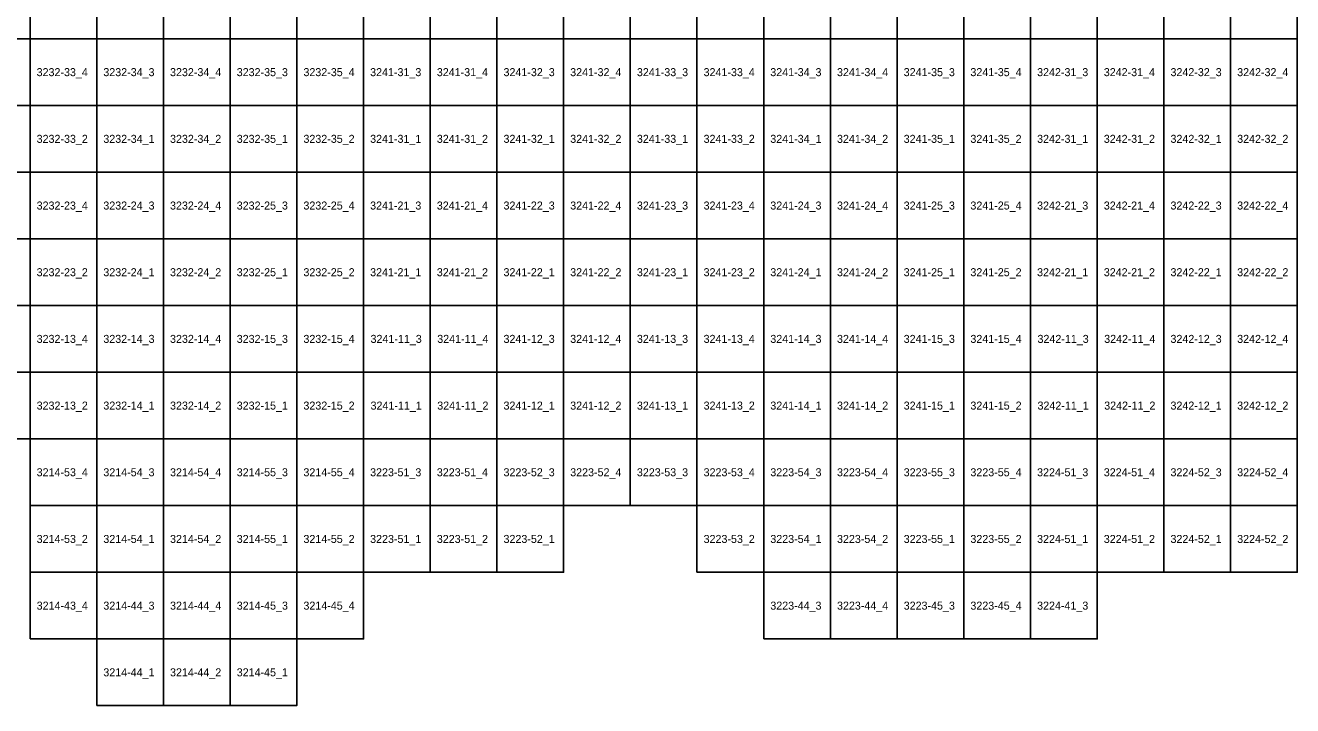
# Model space of a CAD drawing. Extents: x 312500 to 765000, y 172500 to 440000.
# Drawn here: x 437325 to 484827, y 240000 to 265505 of the extents above; entities that cross this region are included whole.
import ezdxf

# ---------------------------------------------------------------- set-up
doc = ezdxf.new("R2010")
doc.units = 0
doc.layers.add('Topo5_ramis_TKS2025', color=7, linetype='Continuous')
doc.layers.add('Topo5_ramis_TKS2025_Nr', color=7, linetype='Continuous')

msp = doc.modelspace()

# ---------------------------------------------------------------- linework, layer by layer
at = {"layer": 'Topo5_ramis_TKS2025'}
for points in [[(435000, 265000), (435000, 267500), (437500, 267500), (437500, 265000), (435000, 265000)], [(437500, 265000), (437500, 267500), (440000, 267500), (440000, 265000), (437500, 265000)], [(440000, 265000), (440000, 267500), (442500, 267500), (442500, 265000), (440000, 265000)], [(442500, 265000), (442500, 267500), (445000, 267500), (445000, 265000), (442500, 265000)], [(445000, 265000), (445000, 267500), (447500, 267500), (447500, 265000), (445000, 265000)], [(447500, 265000), (447500, 267500), (450000, 267500), (450000, 265000), (447500, 265000)], [(450000, 265000), (450000, 267500), (452500, 267500), (452500, 265000), (450000, 265000)], [(452500, 265000), (452500, 267500), (455000, 267500), (455000, 265000), (452500, 265000)], [(455000, 265000), (455000, 267500), (457500, 267500), (457500, 265000), (455000, 265000)], [(457500, 265000), (457500, 267500), (460000, 267500), (460000, 265000), (457500, 265000)], [(460000, 265000), (460000, 267500), (462500, 267500), (462500, 265000), (460000, 265000)], [(462500, 265000), (462500, 267500), (465000, 267500), (465000, 265000), (462500, 265000)], [(465000, 265000), (465000, 267500), (467500, 267500), (467500, 265000), (465000, 265000)], [(467500, 265000), (467500, 267500), (470000, 267500), (470000, 265000), (467500, 265000)], [(470000, 265000), (470000, 267500), (472500, 267500), (472500, 265000), (470000, 265000)], [(472500, 265000), (472500, 267500), (475000, 267500), (475000, 265000), (472500, 265000)], [(475000, 265000), (475000, 267500), (477500, 267500), (477500, 265000), (475000, 265000)], [(477500, 265000), (477500, 267500), (480000, 267500), (480000, 265000), (477500, 265000)], [(480000, 265000), (480000, 267500), (482500, 267500), (482500, 265000), (480000, 265000)], [(482500, 265000), (482500, 267500), (485000, 267500), (485000, 265000), (482500, 265000)], [(435000, 262500), (435000, 265000), (437500, 265000), (437500, 262500), (435000, 262500)], [(437500, 262500), (437500, 265000), (440000, 265000), (440000, 262500), (437500, 262500)], [(440000, 262500), (440000, 265000), (442500, 265000), (442500, 262500), (440000, 262500)], [(442500, 262500), (442500, 265000), (445000, 265000), (445000, 262500), (442500, 262500)], [(445000, 262500), (445000, 265000), (447500, 265000), (447500, 262500), (445000, 262500)], [(447500, 262500), (447500, 265000), (450000, 265000), (450000, 262500), (447500, 262500)], [(450000, 262500), (450000, 265000), (452500, 265000), (452500, 262500), (450000, 262500)], [(452500, 262500), (452500, 265000), (455000, 265000), (455000, 262500), (452500, 262500)], [(455000, 262500), (455000, 265000), (457500, 265000), (457500, 262500), (455000, 262500)], [(457500, 262500), (457500, 265000), (460000, 265000), (460000, 262500), (457500, 262500)], [(460000, 262500), (460000, 265000), (462500, 265000), (462500, 262500), (460000, 262500)], [(462500, 262500), (462500, 265000), (465000, 265000), (465000, 262500), (462500, 262500)], [(465000, 262500), (465000, 265000), (467500, 265000), (467500, 262500), (465000, 262500)], [(467500, 262500), (467500, 265000), (470000, 265000), (470000, 262500), (467500, 262500)], [(470000, 262500), (470000, 265000), (472500, 265000), (472500, 262500), (470000, 262500)], [(472500, 262500), (472500, 265000), (475000, 265000), (475000, 262500), (472500, 262500)], [(475000, 262500), (475000, 265000), (477500, 265000), (477500, 262500), (475000, 262500)], [(477500, 262500), (477500, 265000), (480000, 265000), (480000, 262500), (477500, 262500)], [(480000, 262500), (480000, 265000), (482500, 265000), (482500, 262500), (480000, 262500)], [(482500, 262500), (482500, 265000), (485000, 265000), (485000, 262500), (482500, 262500)], [(435000, 260000), (435000, 262500), (437500, 262500), (437500, 260000), (435000, 260000)], [(437500, 260000), (437500, 262500), (440000, 262500), (440000, 260000), (437500, 260000)], [(440000, 260000), (440000, 262500), (442500, 262500), (442500, 260000), (440000, 260000)], [(442500, 260000), (442500, 262500), (445000, 262500), (445000, 260000), (442500, 260000)], [(445000, 260000), (445000, 262500), (447500, 262500), (447500, 260000), (445000, 260000)], [(447500, 260000), (447500, 262500), (450000, 262500), (450000, 260000), (447500, 260000)], [(450000, 260000), (450000, 262500), (452500, 262500), (452500, 260000), (450000, 260000)], [(452500, 260000), (452500, 262500), (455000, 262500), (455000, 260000), (452500, 260000)], [(455000, 260000), (455000, 262500), (457500, 262500), (457500, 260000), (455000, 260000)], [(457500, 260000), (457500, 262500), (460000, 262500), (460000, 260000), (457500, 260000)], [(460000, 260000), (460000, 262500), (462500, 262500), (462500, 260000), (460000, 260000)], [(462500, 260000), (462500, 262500), (465000, 262500), (465000, 260000), (462500, 260000)], [(465000, 260000), (465000, 262500), (467500, 262500), (467500, 260000), (465000, 260000)], [(467500, 260000), (467500, 262500), (470000, 262500), (470000, 260000), (467500, 260000)], [(470000, 260000), (470000, 262500), (472500, 262500), (472500, 260000), (470000, 260000)], [(472500, 260000), (472500, 262500), (475000, 262500), (475000, 260000), (472500, 260000)], [(475000, 260000), (475000, 262500), (477500, 262500), (477500, 260000), (475000, 260000)], [(477500, 260000), (477500, 262500), (480000, 262500), (480000, 260000), (477500, 260000)], [(480000, 260000), (480000, 262500), (482500, 262500), (482500, 260000), (480000, 260000)], [(482500, 260000), (482500, 262500), (485000, 262500), (485000, 260000), (482500, 260000)], [(435000, 257500), (435000, 260000), (437500, 260000), (437500, 257500), (435000, 257500)], [(437500, 257500), (437500, 260000), (440000, 260000), (440000, 257500), (437500, 257500)], [(440000, 257500), (440000, 260000), (442500, 260000), (442500, 257500), (440000, 257500)], [(442500, 257500), (442500, 260000), (445000, 260000), (445000, 257500), (442500, 257500)], [(445000, 257500), (445000, 260000), (447500, 260000), (447500, 257500), (445000, 257500)], [(447500, 257500), (447500, 260000), (450000, 260000), (450000, 257500), (447500, 257500)], [(450000, 257500), (450000, 260000), (452500, 260000), (452500, 257500), (450000, 257500)], [(452500, 257500), (452500, 260000), (455000, 260000), (455000, 257500), (452500, 257500)], [(455000, 257500), (455000, 260000), (457500, 260000), (457500, 257500), (455000, 257500)], [(457500, 257500), (457500, 260000), (460000, 260000), (460000, 257500), (457500, 257500)], [(460000, 257500), (460000, 260000), (462500, 260000), (462500, 257500), (460000, 257500)], [(462500, 257500), (462500, 260000), (465000, 260000), (465000, 257500), (462500, 257500)], [(465000, 257500), (465000, 260000), (467500, 260000), (467500, 257500), (465000, 257500)], [(467500, 257500), (467500, 260000), (470000, 260000), (470000, 257500), (467500, 257500)], [(470000, 257500), (470000, 260000), (472500, 260000), (472500, 257500), (470000, 257500)], [(472500, 257500), (472500, 260000), (475000, 260000), (475000, 257500), (472500, 257500)], [(475000, 257500), (475000, 260000), (477500, 260000), (477500, 257500), (475000, 257500)], [(477500, 257500), (477500, 260000), (480000, 260000), (480000, 257500), (477500, 257500)], [(480000, 257500), (480000, 260000), (482500, 260000), (482500, 257500), (480000, 257500)], [(482500, 257500), (482500, 260000), (485000, 260000), (485000, 257500), (482500, 257500)], [(435000, 255000), (435000, 257500), (437500, 257500), (437500, 255000), (435000, 255000)], [(437500, 255000), (437500, 257500), (440000, 257500), (440000, 255000), (437500, 255000)], [(440000, 255000), (440000, 257500), (442500, 257500), (442500, 255000), (440000, 255000)], [(442500, 255000), (442500, 257500), (445000, 257500), (445000, 255000), (442500, 255000)], [(445000, 255000), (445000, 257500), (447500, 257500), (447500, 255000), (445000, 255000)], [(447500, 255000), (447500, 257500), (450000, 257500), (450000, 255000), (447500, 255000)], [(450000, 255000), (450000, 257500), (452500, 257500), (452500, 255000), (450000, 255000)], [(452500, 255000), (452500, 257500), (455000, 257500), (455000, 255000), (452500, 255000)], [(455000, 255000), (455000, 257500), (457500, 257500), (457500, 255000), (455000, 255000)], [(457500, 255000), (457500, 257500), (460000, 257500), (460000, 255000), (457500, 255000)], [(460000, 255000), (460000, 257500), (462500, 257500), (462500, 255000), (460000, 255000)], [(462500, 255000), (462500, 257500), (465000, 257500), (465000, 255000), (462500, 255000)], [(465000, 255000), (465000, 257500), (467500, 257500), (467500, 255000), (465000, 255000)], [(467500, 255000), (467500, 257500), (470000, 257500), (470000, 255000), (467500, 255000)], [(470000, 255000), (470000, 257500), (472500, 257500), (472500, 255000), (470000, 255000)], [(472500, 255000), (472500, 257500), (475000, 257500), (475000, 255000), (472500, 255000)], [(475000, 255000), (475000, 257500), (477500, 257500), (477500, 255000), (475000, 255000)], [(477500, 255000), (477500, 257500), (480000, 257500), (480000, 255000), (477500, 255000)], [(480000, 255000), (480000, 257500), (482500, 257500), (482500, 255000), (480000, 255000)], [(482500, 255000), (482500, 257500), (485000, 257500), (485000, 255000), (482500, 255000)], [(435000, 252500), (435000, 255000), (437500, 255000), (437500, 252500), (435000, 252500)], [(437500, 252500), (437500, 255000), (440000, 255000), (440000, 252500), (437500, 252500)], [(440000, 252500), (440000, 255000), (442500, 255000), (442500, 252500), (440000, 252500)], [(442500, 252500), (442500, 255000), (445000, 255000), (445000, 252500), (442500, 252500)], [(445000, 252500), (445000, 255000), (447500, 255000), (447500, 252500), (445000, 252500)], [(447500, 252500), (447500, 255000), (450000, 255000), (450000, 252500), (447500, 252500)], [(450000, 252500), (450000, 255000), (452500, 255000), (452500, 252500), (450000, 252500)], [(452500, 252500), (452500, 255000), (455000, 255000), (455000, 252500), (452500, 252500)], [(455000, 252500), (455000, 255000), (457500, 255000), (457500, 252500), (455000, 252500)], [(457500, 252500), (457500, 255000), (460000, 255000), (460000, 252500), (457500, 252500)], [(460000, 252500), (460000, 255000), (462500, 255000), (462500, 252500), (460000, 252500)], [(462500, 252500), (462500, 255000), (465000, 255000), (465000, 252500), (462500, 252500)], [(465000, 252500), (465000, 255000), (467500, 255000), (467500, 252500), (465000, 252500)], [(467500, 252500), (467500, 255000), (470000, 255000), (470000, 252500), (467500, 252500)], [(470000, 252500), (470000, 255000), (472500, 255000), (472500, 252500), (470000, 252500)], [(472500, 252500), (472500, 255000), (475000, 255000), (475000, 252500), (472500, 252500)], [(475000, 252500), (475000, 255000), (477500, 255000), (477500, 252500), (475000, 252500)], [(477500, 252500), (477500, 255000), (480000, 255000), (480000, 252500), (477500, 252500)], [(480000, 252500), (480000, 255000), (482500, 255000), (482500, 252500), (480000, 252500)], [(482500, 252500), (482500, 255000), (485000, 255000), (485000, 252500), (482500, 252500)], [(435000, 250000), (435000, 252500), (437500, 252500), (437500, 250000), (435000, 250000)], [(437500, 250000), (437500, 252500), (440000, 252500), (440000, 250000), (437500, 250000)], [(440000, 250000), (440000, 252500), (442500, 252500), (442500, 250000), (440000, 250000)], [(442500, 250000), (442500, 252500), (445000, 252500), (445000, 250000), (442500, 250000)], [(445000, 250000), (445000, 252500), (447500, 252500), (447500, 250000), (445000, 250000)], [(447500, 250000), (447500, 252500), (450000, 252500), (450000, 250000), (447500, 250000)], [(450000, 250000), (450000, 252500), (452500, 252500), (452500, 250000), (450000, 250000)], [(452500, 250000), (452500, 252500), (455000, 252500), (455000, 250000), (452500, 250000)], [(455000, 250000), (455000, 252500), (457500, 252500), (457500, 250000), (455000, 250000)], [(457500, 250000), (457500, 252500), (460000, 252500), (460000, 250000), (457500, 250000)], [(460000, 250000), (460000, 252500), (462500, 252500), (462500, 250000), (460000, 250000)], [(462500, 250000), (462500, 252500), (465000, 252500), (465000, 250000), (462500, 250000)], [(465000, 250000), (465000, 252500), (467500, 252500), (467500, 250000), (465000, 250000)], [(467500, 250000), (467500, 252500), (470000, 252500), (470000, 250000), (467500, 250000)], [(470000, 250000), (470000, 252500), (472500, 252500), (472500, 250000), (470000, 250000)], [(472500, 250000), (472500, 252500), (475000, 252500), (475000, 250000), (472500, 250000)], [(475000, 250000), (475000, 252500), (477500, 252500), (477500, 250000), (475000, 250000)], [(477500, 250000), (477500, 252500), (480000, 252500), (480000, 250000), (477500, 250000)], [(480000, 250000), (480000, 252500), (482500, 252500), (482500, 250000), (480000, 250000)], [(482500, 250000), (482500, 252500), (485000, 252500), (485000, 250000), (482500, 250000)], [(437500, 247500), (437500, 250000), (440000, 250000), (440000, 247500), (437500, 247500)], [(440000, 247500), (440000, 250000), (442500, 250000), (442500, 247500), (440000, 247500)], [(442500, 247500), (442500, 250000), (445000, 250000), (445000, 247500), (442500, 247500)], [(445000, 247500), (445000, 250000), (447500, 250000), (447500, 247500), (445000, 247500)], [(447500, 247500), (447500, 250000), (450000, 250000), (450000, 247500), (447500, 247500)], [(450000, 247500), (450000, 250000), (452500, 250000), (452500, 247500), (450000, 247500)], [(452500, 247500), (452500, 250000), (455000, 250000), (455000, 247500), (452500, 247500)], [(455000, 247500), (455000, 250000), (457500, 250000), (457500, 247500), (455000, 247500)], [(457500, 247500), (457500, 250000), (460000, 250000), (460000, 247500), (457500, 247500)], [(460000, 247500), (460000, 250000), (462500, 250000), (462500, 247500), (460000, 247500)], [(462500, 247500), (462500, 250000), (465000, 250000), (465000, 247500), (462500, 247500)], [(465000, 247500), (465000, 250000), (467500, 250000), (467500, 247500), (465000, 247500)], [(467500, 247500), (467500, 250000), (470000, 250000), (470000, 247500), (467500, 247500)], [(470000, 247500), (470000, 250000), (472500, 250000), (472500, 247500), (470000, 247500)], [(472500, 247500), (472500, 250000), (475000, 250000), (475000, 247500), (472500, 247500)], [(475000, 247500), (475000, 250000), (477500, 250000), (477500, 247500), (475000, 247500)], [(477500, 247500), (477500, 250000), (480000, 250000), (480000, 247500), (477500, 247500)], [(480000, 247500), (480000, 250000), (482500, 250000), (482500, 247500), (480000, 247500)], [(482500, 247500), (482500, 250000), (485000, 250000), (485000, 247500), (482500, 247500)], [(437500, 245000), (437500, 247500), (440000, 247500), (440000, 245000), (437500, 245000)], [(440000, 245000), (440000, 247500), (442500, 247500), (442500, 245000), (440000, 245000)], [(442500, 245000), (442500, 247500), (445000, 247500), (445000, 245000), (442500, 245000)], [(445000, 245000), (445000, 247500), (447500, 247500), (447500, 245000), (445000, 245000)], [(447500, 245000), (447500, 247500), (450000, 247500), (450000, 245000), (447500, 245000)], [(450000, 245000), (450000, 247500), (452500, 247500), (452500, 245000), (450000, 245000)], [(452500, 245000), (452500, 247500), (455000, 247500), (455000, 245000), (452500, 245000)], [(455000, 245000), (455000, 247500), (457500, 247500), (457500, 245000), (455000, 245000)], [(462500, 245000), (462500, 247500), (465000, 247500), (465000, 245000), (462500, 245000)], [(465000, 245000), (465000, 247500), (467500, 247500), (467500, 245000), (465000, 245000)], [(467500, 245000), (467500, 247500), (470000, 247500), (470000, 245000), (467500, 245000)], [(470000, 245000), (470000, 247500), (472500, 247500), (472500, 245000), (470000, 245000)], [(472500, 245000), (472500, 247500), (475000, 247500), (475000, 245000), (472500, 245000)], [(475000, 245000), (475000, 247500), (477500, 247500), (477500, 245000), (475000, 245000)], [(477500, 245000), (477500, 247500), (480000, 247500), (480000, 245000), (477500, 245000)], [(480000, 245000), (480000, 247500), (482500, 247500), (482500, 245000), (480000, 245000)], [(482500, 245000), (482500, 247500), (485000, 247500), (485000, 245000), (482500, 245000)], [(437500, 242500), (437500, 245000), (440000, 245000), (440000, 242500), (437500, 242500)], [(440000, 242500), (440000, 245000), (442500, 245000), (442500, 242500), (440000, 242500)], [(442500, 242500), (442500, 245000), (445000, 245000), (445000, 242500), (442500, 242500)], [(445000, 242500), (445000, 245000), (447500, 245000), (447500, 242500), (445000, 242500)], [(447500, 242500), (447500, 245000), (450000, 245000), (450000, 242500), (447500, 242500)], [(465000, 242500), (465000, 245000), (467500, 245000), (467500, 242500), (465000, 242500)], [(467500, 242500), (467500, 245000), (470000, 245000), (470000, 242500), (467500, 242500)], [(470000, 242500), (470000, 245000), (472500, 245000), (472500, 242500), (470000, 242500)], [(472500, 242500), (472500, 245000), (475000, 245000), (475000, 242500), (472500, 242500)], [(475000, 242500), (475000, 245000), (477500, 245000), (477500, 242500), (475000, 242500)], [(440000, 240000), (440000, 242500), (442500, 242500), (442500, 240000), (440000, 240000)], [(442500, 240000), (442500, 242500), (445000, 242500), (445000, 240000), (442500, 240000)], [(445000, 240000), (445000, 242500), (447500, 242500), (447500, 240000), (445000, 240000)]]:
    msp.add_lwpolyline(points, dxfattribs=at)

# ---------------------------------------------------------------- texts
at = {"layer": 'Topo5_ramis_TKS2025_Nr'}
for s, p in [('3232-33_4', (437748, 263600)), ('3232-34_3', (440248, 263600)), ('3232-34_4', (442748, 263600)), ('3232-35_3', (445248, 263600)), ('3232-35_4', (447748, 263600)), ('3241-31_3', (450248, 263600)), ('3241-31_4', (452748, 263600)), ('3241-32_3', (455248, 263600)), ('3241-32_4', (457748, 263600)), ('3241-33_3', (460248, 263600)), ('3241-33_4', (462748, 263600)), ('3241-34_3', (465248, 263600)), ('3241-34_4', (467748, 263600)), ('3241-35_3', (470248, 263600)), ('3241-35_4', (472748, 263600)), ('3242-31_3', (475248, 263600)), ('3242-31_4', (477748, 263600)), ('3242-32_3', (480248, 263600)), ('3242-32_4', (482748, 263600)), ('3232-33_2', (437748, 261100)), ('3232-34_1', (440248, 261100)), ('3232-34_2', (442748, 261100)), ('3232-35_1', (445248, 261100)), ('3232-35_2', (447748, 261100)), ('3241-31_1', (450248, 261100)), ('3241-31_2', (452748, 261100)), ('3241-32_1', (455248, 261100)), ('3241-32_2', (457748, 261100)), ('3241-33_1', (460248, 261100)), ('3241-33_2', (462748, 261100)), ('3241-34_1', (465248, 261100)), ('3241-34_2', (467748, 261100)), ('3241-35_1', (470248, 261100)), ('3241-35_2', (472748, 261100)), ('3242-31_1', (475248, 261100)), ('3242-31_2', (477748, 261100)), ('3242-32_1', (480248, 261100)), ('3242-32_2', (482748, 261100)), ('3232-23_4', (437748, 258600)), ('3232-24_3', (440248, 258600)), ('3232-24_4', (442748, 258600)), ('3232-25_3', (445248, 258600)), ('3232-25_4', (447748, 258600)), ('3241-21_3', (450248, 258600)), ('3241-21_4', (452748, 258600)), ('3241-22_3', (455248, 258600)), ('3241-22_4', (457748, 258600)), ('3241-23_3', (460248, 258600)), ('3241-23_4', (462748, 258600)), ('3241-24_3', (465248, 258600)), ('3241-24_4', (467748, 258600)), ('3241-25_3', (470248, 258600)), ('3241-25_4', (472748, 258600)), ('3242-21_3', (475248, 258600)), ('3242-21_4', (477748, 258600)), ('3242-22_3', (480248, 258600)), ('3242-22_4', (482748, 258600)), ('3232-23_2', (437748, 256100)), ('3232-24_1', (440248, 256100)), ('3232-24_2', (442748, 256100)), ('3232-25_1', (445248, 256100)), ('3232-25_2', (447748, 256100)), ('3241-21_1', (450248, 256100)), ('3241-21_2', (452748, 256100)), ('3241-22_1', (455248, 256100)), ('3241-22_2', (457748, 256100)), ('3241-23_1', (460248, 256100)), ('3241-23_2', (462748, 256100)), ('3241-24_1', (465248, 256100)), ('3241-24_2', (467748, 256100)), ('3241-25_1', (470248, 256100)), ('3241-25_2', (472748, 256100)), ('3242-21_1', (475248, 256100)), ('3242-21_2', (477748, 256100)), ('3242-22_1', (480248, 256100)), ('3242-22_2', (482748, 256100)), ('3232-13_4', (437748, 253600)), ('3232-14_3', (440248, 253600)), ('3232-14_4', (442748, 253600)), ('3232-15_3', (445248, 253600)), ('3232-15_4', (447748, 253600)), ('3241-11_3', (450264, 253600)), ('3241-11_4', (452764, 253600)), ('3241-12_3', (455248, 253600)), ('3241-12_4', (457748, 253600)), ('3241-13_3', (460248, 253600)), ('3241-13_4', (462748, 253600)), ('3241-14_3', (465248, 253600)), ('3241-14_4', (467748, 253600)), ('3241-15_3', (470248, 253600)), ('3241-15_4', (472748, 253600)), ('3242-11_3', (475264, 253600)), ('3242-11_4', (477764, 253600)), ('3242-12_3', (480248, 253600)), ('3242-12_4', (482748, 253600)), ('3232-13_2', (437748, 251100)), ('3232-14_1', (440248, 251100)), ('3232-14_2', (442748, 251100)), ('3232-15_1', (445248, 251100)), ('3232-15_2', (447748, 251100)), ('3241-11_1', (450264, 251100)), ('3241-11_2', (452764, 251100)), ('3241-12_1', (455248, 251100)), ('3241-12_2', (457748, 251100)), ('3241-13_1', (460248, 251100)), ('3241-13_2', (462748, 251100)), ('3241-14_1', (465248, 251100)), ('3241-14_2', (467748, 251100)), ('3241-15_1', (470248, 251100)), ('3241-15_2', (472748, 251100)), ('3242-11_1', (475264, 251100)), ('3242-11_2', (477764, 251100)), ('3242-12_1', (480248, 251100)), ('3242-12_2', (482748, 251100)), ('3214-53_4', (437748, 248600)), ('3214-54_3', (440248, 248600)), ('3214-54_4', (442748, 248600)), ('3214-55_3', (445248, 248600)), ('3214-55_4', (447748, 248600)), ('3223-51_3', (450248, 248600)), ('3223-51_4', (452748, 248600)), ('3223-52_3', (455248, 248600)), ('3223-52_4', (457748, 248600)), ('3223-53_3', (460248, 248600)), ('3223-53_4', (462748, 248600)), ('3223-54_3', (465248, 248600)), ('3223-54_4', (467748, 248600)), ('3223-55_3', (470248, 248600)), ('3223-55_4', (472748, 248600)), ('3224-51_3', (475248, 248600)), ('3224-51_4', (477748, 248600)), ('3224-52_3', (480248, 248600)), ('3224-52_4', (482748, 248600)), ('3214-53_2', (437748, 246100)), ('3214-54_1', (440248, 246100)), ('3214-54_2', (442748, 246100)), ('3214-55_1', (445248, 246100)), ('3214-55_2', (447748, 246100)), ('3223-51_1', (450248, 246100)), ('3223-51_2', (452748, 246100)), ('3223-52_1', (455248, 246100)), ('3223-53_2', (462748, 246100)), ('3223-54_1', (465248, 246100)), ('3223-54_2', (467748, 246100)), ('3223-55_1', (470248, 246100)), ('3223-55_2', (472748, 246100)), ('3224-51_1', (475248, 246100)), ('3224-51_2', (477748, 246100)), ('3224-52_1', (480248, 246100)), ('3224-52_2', (482748, 246100)), ('3214-43_4', (437748, 243600)), ('3214-44_3', (440248, 243600)), ('3214-44_4', (442748, 243600)), ('3214-45_3', (445248, 243600)), ('3214-45_4', (447748, 243600)), ('3223-44_3', (465248, 243600)), ('3223-44_4', (467748, 243600)), ('3223-45_3', (470248, 243600)), ('3223-45_4', (472748, 243600)), ('3224-41_3', (475248, 243600)), ('3214-44_1', (440248, 241100)), ('3214-44_2', (442748, 241100)), ('3214-45_1', (445248, 241100))]:
    msp.add_text(s, height=300, dxfattribs=at).set_placement(p)

doc.saveas('drawing.dxf')
